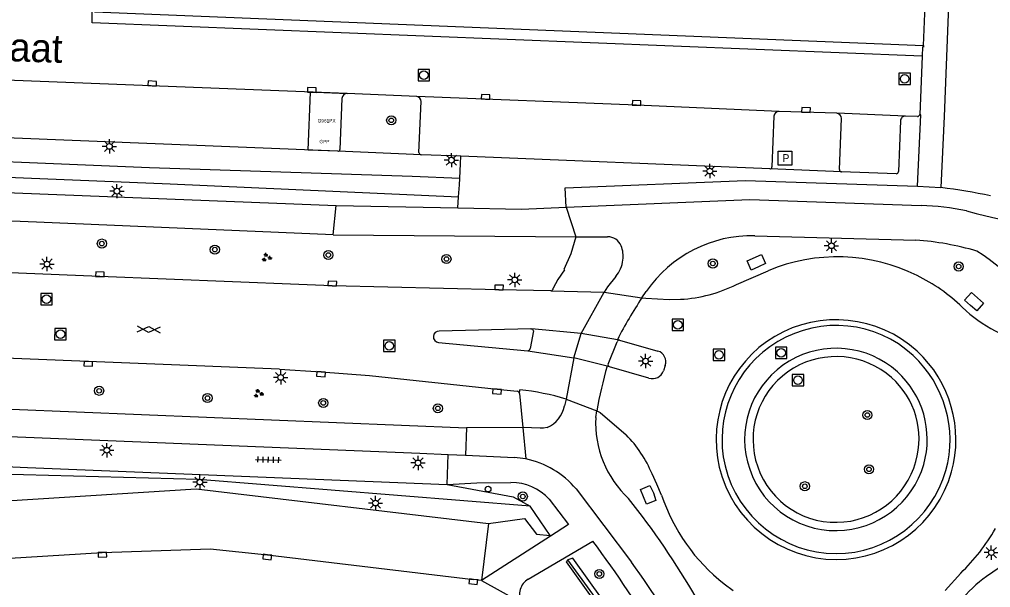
# Model space of a CAD drawing. Extents: x 132994 to 136000, y 393499 to 395512.
# Drawn here: x 133765.3 to 133850.3, y 394656.2 to 394705.8 of the extents above; entities that cross this region are included whole.
import ezdxf

# ---------------------------------------------------------------- set-up
doc = ezdxf.new("R2010")
doc.units = 0
for name, color, linetype in [('bp-anno-kenteken', 7, 'Continuous'), ('bp-grn-parkeervak', 7, 'Continuous'), ('gg-afsc-hekwerk', 7, 'Continuous'), ('gg-anno-openbare ruimte label', 7, 'Continuous'), ('gg-knt-verharding', 7, 'Continuous'), ('gg-knt-verharding nz', 7, 'Continuous'), ('gt-grn-groengrens', 7, 'Continuous'), ('gt-grn-weggrens', 7, 'Continuous'), ('gt-symb-boom', 7, 'Continuous'), ('gt-symb-brandput', 7, 'Continuous'), ('gt-symb-gesloten verharding', 7, 'Continuous'), ('gt-symb-groenvak', 7, 'Continuous'), ('gt-symb-kolk', 7, 'Continuous'), ('gt-symb-lichtmast', 7, 'Continuous'), ('gt-symb-rioolschacht', 7, 'Continuous'), ('gt-symb-tegel verharding', 7, 'Continuous'), ('gt-symb-verkeersbordpaal', 7, 'Continuous'), ('kenmerkpunt gehandicapten parkeerplaats', 7, 'Continuous')]:
    doc.layers.add(name, color=color, linetype=linetype)

# ---------------------------------------------------------------- blocks, each defined once
blk = doc.blocks.new('gt0-KOLK')
at = {"layer": 'gt-symb-kolk'}
blk.add_lwpolyline([(0, 0), (0.375, 0), (0.375, 0.4), (-0.375, 0.4), (-0.375, 0), (0, 0)], dxfattribs=at)
blk = doc.blocks.new('gt0-RS')
at = {"layer": 'gt-symb-rioolschacht'}
blk.add_lwpolyline([(-0.5, -0.5), (0.5, -0.5), (0.5, 0.5), (-0.5, 0.5)], close=True, dxfattribs=at)
blk.add_circle((0, 0), 0.375, dxfattribs=at)
blk = doc.blocks.new('gt0-BOOM')
at = {"layer": 'gt-symb-boom'}
for radius in [0.4, 0.2]:
    blk.add_circle((0, 0), radius, dxfattribs=at)
blk = doc.blocks.new('gt0-LMAST')
at = {"layer": 'gt-symb-lichtmast'}
for p, q in [((-0.182, 0.173), (-0.447, 0.438)), ((-0.005, 0.246), (-0.005, 0.621)), ((0.172, 0.173), (0.437, 0.438)), ((-0.255, -0.004), (-0.63, -0.004)), ((-0.182, -0.181), (-0.447, -0.446)), ((-0.005, -0.254), (-0.005, -0.629)), ((0.437, -0.446), (0.172, -0.181)), ((0.245, -0.004), (0.62, -0.004))]:
    blk.add_line(p, q, dxfattribs=at)
blk.add_circle((-0.005, -0.004), 0.25, dxfattribs=at)
blk = doc.blocks.new('gt0-BPUT')
at = {"layer": 'gt-symb-brandput'}
blk.add_lwpolyline([(-0.599, -0.599), (-0.599, 0.601), (0.601, 0.601), (0.601, -0.599)], close=True, dxfattribs=at)
blk.add_text('P', height=0.7, dxfattribs=at).set_placement((-0.233, -0.35))
blk = doc.blocks.new('gt0-VPAAL')
at = {"layer": 'gt-symb-verkeersbordpaal'}
blk.add_circle((0, 0), 0.25, dxfattribs=at)
blk = doc.blocks.new('gt0-GRVAK')
at = {"layer": 'gt-symb-groenvak'}
for p, q in [((-0.11, 0.189), (-0.228, 0.24)), ((-0.182, 0.153), (0.088, 0.153)), ((-0.091, 0.211), (-0.156, 0.322)), ((-0.047, 0.214), (-0.047, 0.393)), ((-0.004, 0.211), (0.061, 0.322)), ((0.015, 0.189), (0.133, 0.24)), ((0.262, -0.052), (0.197, 0.059)), ((0.305, -0.049), (0.305, 0.13)), ((0.349, -0.052), (0.414, 0.059)), ((-0.245, -0.228), (-0.363, -0.177)), ((-0.318, -0.264), (-0.047, -0.264)), ((-0.226, -0.206), (-0.291, -0.095)), ((-0.183, -0.203), (-0.183, -0.024)), ((-0.139, -0.206), (-0.074, -0.095)), ((-0.12, -0.228), (-0.002, -0.177)), ((0.243, -0.074), (0.125, -0.023)), ((0.17, -0.11), (0.441, -0.11)), ((0.368, -0.074), (0.486, -0.023))]:
    blk.add_line(p, q, dxfattribs=at)
blk = doc.blocks.new('gt0-GESVH1')
at = {"layer": 'gt-symb-gesloten verharding'}
for p, q in [((-0.992, -0.261), (0.008, 0.239)), ((0.008, -0.261), (-0.992, 0.239)), ((0.008, 0.239), (1.008, -0.261)), ((1.008, 0.239), (0.008, -0.261))]:
    blk.add_line(p, q, dxfattribs=at)
blk = doc.blocks.new('gt0-TEG1')
at = {"layer": 'gt-symb-tegel verharding'}
for p, q in [((-1.125, 0), (1.125, 0)), ((-0.9, -0.25), (-0.9, 0.25)), ((-0.45, -0.25), (-0.45, 0.25)), ((0, -0.25), (0, 0.25)), ((0.45, -0.25), (0.45, 0.25)), ((0.9, -0.25), (0.9, 0.25))]:
    blk.add_line(p, q, dxfattribs=at)

msp = doc.modelspace()

# ---------------------------------------------------------------- linework, layer by layer
at = {"layer": 'bp-grn-parkeervak'}
msp.add_line((133793.533, 394698.926), (133793.351, 394694.482), dxfattribs=at)
msp.add_lwpolyline([(133793.162, 394694.32), (133790.567, 394694.425), (133790.771, 394699.48), (133791.262, 394699.462), (133791.262, 394699.471), (133793.982, 394699.363)], dxfattribs=at)
for centre, radius, start, end in [((133793.991, 394698.905), 0.458, 91.12258, 177.32548), ((133793.169, 394694.503), 0.183, 267.75596, 353.44663)]:
    msp.add_arc(centre, radius, start, end, dxfattribs=at)
at = {"layer": 'gg-afsc-hekwerk'}
for p, q in [((133811.73, 394660.735), (133809.991, 394663.299)), ((133811.775, 394660.669), (133811.73, 394660.735))]:
    msp.add_line(p, q, dxfattribs=at)
for points in [[(133809.991, 394663.299), (133780.983, 394665.622), (133728.496, 394667.016)], [(133823.262, 394642.826), (133822.714, 394645.643), (133813.273, 394658.598)]]:
    msp.add_lwpolyline(points, dxfattribs=at)
at = {"layer": 'gg-knt-verharding'}
for p, q in [((133844.381, 394703.553), (133844.562, 394708.084)), ((133771.889, 394706.495), (133844.381, 394703.553)), ((133844.259, 394702.617), (133844.053, 394697.536)), ((133800.072, 394699.109), (133793.982, 394699.363)), ((133793.533, 394698.926), (133793.351, 394694.482)), ((133800.258, 394694.222), (133800.444, 394698.656)), ((133836.796, 394697.632), (133831.762, 394697.804)), ((133831.31, 394697.39), (133831.132, 394692.949)), ((133837.041, 394692.717), (133837.217, 394697.174)), ((133842.369, 394696.964), (133842.199, 394692.539)), ((133843.847, 394697.345), (133842.817, 394697.386)), ((133846.186, 394697.343), (133845.913, 394691.136)), ((133793.162, 394694.32), (133752.945, 394695.94)), ((133803.934, 394693.873), (133800.45, 394694.016)), ((133830.935, 394692.767), (133803.934, 394693.873)), ((133841.996, 394692.337), (133837.228, 394692.511)), ((133752.764, 394691.164), (133793.012, 394689.56)), ((133793.012, 394689.56), (133803.652, 394689.368)), ((133792.754, 394687.001), (133813.989, 394686.847)), ((133813.989, 394686.847), (133816.764, 394686.842)), ((133829.641, 394686.934), (133843.724, 394686.546)), ((133828.033, 394682.67), (133830.788, 394683.874)), ((133792.684, 394682.559), (133789.767, 394682.674)), ((133811.793, 394682.126), (133816.454, 394681.988)), ((133819.766, 394681.514), (133820.147, 394682.068)), ((133810.037, 394678.803), (133802.038, 394678.601)), ((133810.266, 394678.609), (133809.98, 394677.059)), ((133810.037, 394678.803), (133810.107, 394678.796)), ((133814.461, 394678.381), (133810.107, 394678.796)), ((133813.812, 394676.266), (133814.461, 394678.381)), ((133801.984, 394677.601), (133809.778, 394676.874)), ((133816.799, 394675.718), (133817.585, 394677.647)), ((133817.802, 394677.799), (133821.167, 394676.854)), ((133809.778, 394676.874), (133813.812, 394676.266)), ((133821.799, 394675.594), (133821.645, 394675.124)), ((133820.373, 394674.487), (133816.929, 394675.479)), ((133809.05, 394673.14), (133809.095, 394673.47)), ((133809.05, 394673.14), (133809.339, 394670.155)), ((133813.134, 394672.644), (133813.003, 394672.058)), ((133815.726, 394671.046), (133815.82, 394671.63)), ((133816.096, 394671.473), (133818.382, 394669.519)), ((133809.339, 394670.155), (133804.433, 394670.144)), ((133800.346, 394667.913), (133802.831, 394667.804)), ((133802.831, 394667.804), (133804.328, 394667.739)), ((133804.328, 394667.739), (133808.612, 394667.551)), ((133814.006, 394664.802), (133818.837, 394658.407)), ((133806.35, 394661.786), (133805.745, 394656.782)), ((133811.775, 394660.669), (133805.745, 394656.782)), ((133809.826, 394656.9), (133815.474, 394660.234)), ((133853.547, 394659.669), (133849.907, 394657.147)), ((133846.289, 394655.931), (133847.645, 394657.446)), ((133826.957, 394656.496), (133827.744, 394655.93))]:
    msp.add_line(p, q, dxfattribs=at)
for points in [[(133849.337, 394727.82), (133846.684, 394707.826), (133846.606, 394707.833), (133846.186, 394697.343)], [(133844.381, 394703.553), (133844.391, 394703.429), (133844.304, 394703.434), (133844.259, 394702.617)], [(133843.871, 394691.264), (133844.152, 394697.504), (133844.053, 394697.536)], [(133813.135, 394689.426), (133813.059, 394691.11), (133828.831, 394691.768), (133843.871, 394691.264)], [(133813.135, 394689.426), (133829.202, 394690.095), (133844.185, 394689.571)], [(133792.754, 394687.001), (133766.808, 394688.109), (133731.72, 394689.534)], [(133803.652, 394689.368), (133809.223, 394689.268), (133813.135, 394689.426)], [(133813.989, 394686.847), (133813.555, 394685.36), (133812.938, 394683.981), (133812.98, 394683.953), (133812.422, 394683.114), (133812.008, 394682.334)], [(133830.576, 394684.493), (133829.955, 394684.2), (133829.321, 394683.917), (133828.957, 394684.731), (133830.212, 394685.282), (133830.576, 394684.493)], [(133789.767, 394682.674), (133772.353, 394683.357), (133738.902, 394684.743)], [(133817.477, 394683.378), (133816.763, 394682.456), (133816.454, 394681.988)], [(133811.793, 394682.126), (133807.265, 394682.212), (133792.684, 394682.559)], [(133820.108, 394681.478), (133822.139, 394681.369), (133823.148, 394681.376)], [(133849.063, 394680.364), (133848.485, 394680.843), (133847.979, 394681.304), (133848.584, 394681.956), (133849.626, 394681.036), (133849.063, 394680.364)], [(133788.073, 394675.271), (133762.589, 394676.287), (133738.597, 394677.272)], [(133788.073, 394675.271), (133791.712, 394675.033), (133795.929, 394674.716), (133807.106, 394673.514), (133808.858, 394673.338)], [(133728.982, 394673.24), (133736.189, 394672.925), (133804.433, 394670.144)], [(133728.768, 394670.857), (133763.723, 394669.408), (133800.346, 394667.913)], [(133811.483, 394670.16), (133811.163, 394670.095), (133810.851, 394670.094), (133809.339, 394670.155)], [(133728.533, 394668.252), (133762.121, 394666.858), (133766.041, 394666.677), (133802.717, 394665.195)], [(133802.717, 394665.195), (133805.335, 394665.337), (133808.311, 394665.348)], [(133821.483, 394664.264), (133821.078, 394665.212), (133820.648, 394666.123)], [(133752.658, 394663.035), (133780.79, 394664.799), (133806.35, 394661.786)], [(133820.444, 394665.089), (133820.763, 394664.45), (133820.984, 394663.795), (133820.162, 394663.477), (133819.628, 394664.755), (133820.444, 394665.089)], [(133811.658, 394663.905), (133813.343, 394661.68), (133811.775, 394660.669)]]:
    msp.add_lwpolyline(points, dxfattribs=at)
for centre, radius, start, end in [((133793.991, 394698.905), 0.458, 91.12258, 177.32548), ((133800.025, 394698.691), 0.42, 355.19104, 83.5941), ((133831.752, 394697.361), 0.443, 88.67765, 176.29731), ((133836.758, 394697.174), 0.459, 359.97242, 85.20689), ((133842.802, 394696.953), 0.434, 88.07819, 178.49826), ((133843.839, 394697.56), 0.215, 272.09034, 353.58207), ((133793.169, 394694.503), 0.183, 267.75596, 353.44663), ((133800.467, 394694.224), 0.209, 180.67384, 265.29697), ((133830.938, 394692.961), 0.194, 269.14484, 356.32224), ((133837.239, 394692.709), 0.198, 177.66235, 266.80191), ((133841.97, 394692.566), 0.231, 276.46808, 353.24898), ((133841.985, 394654.441), 36.904, 77.05685, 83.89002), ((133843.424, 394665.722), 23.861, 78.59515, 88.17171), ((133857.418, 394720.691), 32.913, 253.62995, 278.07403), ((133816.771, 394685.57), 1.272, 22.22596, 90.32699), ((133829.404, 394675.702), 11.235, 88.79047, 145.48291), ((133815.587, 394685.136), 2.533, 352.45941, 21.16816), ((133841.952, 394661.396), 25.212, 73.68435, 85.96999), ((133836.841, 394669.313), 15.769, 63.73432, 112.57386), ((133839.262, 394669.996), 18.406, 25.13507, 57.92871), ((133815.38, 394685.139), 2.739, 319.96991, 352.9654), ((133836.854, 394669.292), 15.783, 46.19412, 63.80824), ((133811.789, 394682.345), 0.219, 270.97988, 357.12398), ((133822.437, 394693.929), 12.573, 273.24334, 296.4296), ((133856.165, 394689.36), 12.067, 225.9806, 259.74876), ((133836.721, 394669.033), 10.557, 47.69366, 120.45357), ((133836.749, 394669.171), 9.918, 47.35731, 120.99705), ((133802.022, 394678.1), 0.501, 88.19801, 265.62005), ((133810.051, 394678.588), 0.216, 5.67214, 75.07472), ((133836.776, 394669.101), 10.526, 120.89737, 193.24071), ((133817.801, 394677.57), 0.229, 89.7085, 160.31097), ((133836.714, 394669.114), 9.949, 120.65698, 193.40108), ((133809.769, 394677.086), 0.213, 272.3592, 352.61029), ((133820.848, 394675.905), 1.001, 341.87395, 71.40158), ((133836.747, 394669.065), 8.027, 48.1636, 120.73446), ((133836.738, 394669.047), 7.322, 48.58188, 120.51662), ((133836.673, 394669.087), 10.03, 344.51827, 47.36049), ((133836.695, 394669.098), 10.526, 344.45302, 47.34749), ((133816.994, 394675.669), 0.201, 165.97333, 251.11313), ((133836.683, 394669.13), 7.938, 120.58044, 194.28352), ((133820.684, 394675.455), 1.017, 252.20533, 340.99682), ((133836.725, 394669.126), 7.248, 120.74035, 194.47501), ((133836.677, 394669.121), 8.032, 344.28468, 47.52388), ((133836.836, 394669.175), 7.162, 343.96174, 48.49513), ((133808.819, 394673.108), 0.233, 7.79557, 80.44162), ((133806.635, 394651.153), 22.453, 73.17447, 83.7096), ((133810.287, 394672.675), 2.785, 295.42677, 347.19474), ((133824.75, 394670.573), 9.037, 177.00004, 227.08398), ((133810.821, 394662.02), 10.649, 22.66231, 44.76453), ((133808.06, 394659.894), 7.677, 78.39749, 85.87633), ((133808.047, 394659.774), 7.797, 40.15349, 78.47955), ((133836.712, 394669.11), 7.96, 194.0873, 270.8349), ((133836.706, 394669.1), 7.223, 194.31518, 271.01688), ((133836.728, 394669.131), 7.254, 270.83847, 344.5268), ((133836.772, 394669.161), 10.536, 193.56236, 269.85367), ((133836.783, 394669.168), 10.029, 193.60928, 269.74111), ((133836.708, 394669.153), 10.014, 270.17363, 344.1009), ((133836.734, 394669.12), 10.495, 270.06189, 344.28416), ((133836.716, 394669.153), 8.004, 270.8021, 343.98729), ((133808.372, 394660.887), 4.461, 42.56788, 90.78725), ((133764.488, 394620.756), 69.238, 29.86457, 38.60312), ((133837.079, 394669.442), 16.433, 198.36517, 231.97846), ((133836.038, 394669.632), 16.829, 313.60544, 330.41373), ((133715.1, 394586.114), 124.774, 26.68684, 36.44362), ((133747.421, 394606.62), 88.216, 22.94305, 35.94773), ((133810.55, 394655.593), 1.494, 118.96876, 209.86491), ((133855.972, 394648.509), 10.555, 125.0752, 159.66962)]:
    msp.add_arc(centre, radius, start, end, dxfattribs=at)
at = {"layer": 'gg-knt-verharding nz'}
for p, q in [((133793.982, 394699.363), (133753.136, 394700.981)), ((133842.817, 394697.386), (133836.796, 394697.632)), ((133814.461, 394678.381), (133816.454, 394681.988)), ((133816.454, 394681.988), (133819.766, 394681.514)), ((133819.766, 394681.514), (133820.108, 394681.478)), ((133817.618, 394677.842), (133814.461, 394678.381)), ((133817.802, 394677.799), (133817.618, 394677.842)), ((133813.812, 394676.266), (133813.134, 394672.644)), ((133816.729, 394675.531), (133813.812, 394676.266)), ((133816.929, 394675.479), (133816.729, 394675.531)), ((133813.134, 394672.644), (133815.82, 394671.63)), ((133815.82, 394671.63), (133816.096, 394671.473)), ((133787.019, 394659.047), (133805.044, 394656.882)), ((133805.745, 394656.782), (133805.044, 394656.882)), ((133805.745, 394656.782), (133809.254, 394654.849))]:
    msp.add_line(p, q, dxfattribs=at)
for points in [[(133844.259, 394702.617), (133771.681, 394705.557), (133771.697, 394706.519)], [(133831.762, 394697.804), (133819.286, 394698.333), (133800.072, 394699.109)], [(133752.967, 394658.057), (133757.801, 394658.323), (133772.574, 394659.249), (133782.016, 394659.569), (133787.019, 394659.047)]]:
    msp.add_lwpolyline(points, dxfattribs=at)
for centre, radius, start, end in [((133851.869, 394660.271), 38.495, 146.50623, 152.84129), ((133846.794, 394666.469), 31.401, 163.22634, 170.53997)]:
    msp.add_arc(centre, radius, start, end, dxfattribs=at)
at = {"layer": 'gt-grn-groengrens'}
for p, q in [((133800.45, 394694.016), (133793.162, 394694.32)), ((133803.909, 394693.255), (133803.934, 394693.873)), ((133803.831, 394691.932), (133803.909, 394693.255)), ((133837.228, 394692.511), (133830.935, 394692.767)), ((133803.808, 394691.387), (133803.831, 394691.932)), ((133803.726, 394690.326), (133803.808, 394691.387)), ((133803.652, 394689.368), (133803.726, 394690.326))]:
    msp.add_line(p, q, dxfattribs=at)
for points in [[(133803.831, 394691.932), (133799.665, 394692.108), (133776.708, 394692.873), (133752.866, 394693.858)], [(133752.815, 394692.517), (133778.51, 394691.466), (133803.726, 394690.326)], [(133802.717, 394665.195), (133808.49, 394664.116), (133809.991, 394663.299)], [(133806.35, 394661.786), (133809.494, 394662.199), (133810.556, 394660.853), (133811.73, 394660.735)], [(133813.273, 394658.598), (133813.135, 394658.413), (133822.392, 394645.454), (133822.891, 394643.115), (133822.848, 394642.917)], [(133824.473, 394641.192), (133823.677, 394642.927), (133823.087, 394645.679), (133813.706, 394658.758), (133813.273, 394658.598)]]:
    msp.add_lwpolyline(points, dxfattribs=at)
at = {"layer": 'gt-grn-weggrens'}
for p, q in [((133843.871, 394691.264), (133845.913, 394691.136)), ((133792.754, 394687.001), (133793.012, 394689.56)), ((133813.135, 394689.426), (133813.989, 394686.847)), ((133804.433, 394670.144), (133804.328, 394667.739)), ((133809.339, 394670.155), (133809.604, 394667.414)), ((133802.717, 394665.195), (133802.831, 394667.804))]:
    msp.add_line(p, q, dxfattribs=at)

# ---------------------------------------------------------------- block references
at = {"layer": 'gt-symb-boom'}
for p in [(133797.839, 394697.023), (133772.536, 394686.247), (133782.413, 394685.72), (133792.34, 394685.243), (133802.668, 394684.896), (133825.961, 394684.507), (133847.46, 394684.246), (133772.294, 394673.377), (133781.771, 394672.738), (133791.893, 394672.316), (133801.919, 394671.839), (133839.471, 394671.258), (133839.617, 394666.512), (133834.006, 394665.032), (133809.343, 394664.138), (133816.037, 394657.364)]:
    msp.add_blockref('gt0-BOOM', p, dxfattribs=at)
at = {"layer": 'gt-symb-brandput'}
msp.add_blockref('gt0-BPUT', (133832.27, 394693.714), dxfattribs=at)
at = {"layer": 'gt-symb-gesloten verharding', "rotation": -2.292900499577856}
msp.add_blockref('gt0-GESVH1', (133776.629, 394678.746), dxfattribs=at)
at = {"layer": 'gt-symb-groenvak'}
for p in [(133786.927, 394685.035), (133786.217, 394673.131)]:
    msp.add_blockref('gt0-GRVAK', p, dxfattribs=at)
at = {"layer": 'gt-symb-kolk'}
for p, rotation in [((133776.929, 394700.044), -2.3328628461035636), ((133790.887, 394699.476), -2.0906300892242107), ((133806.079, 394698.872), -2.340926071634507), ((133819.286, 394698.333), -2.4215531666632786), ((133834.101, 394697.73), -2.0825652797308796), ((133772.353, 394683.357), -2.35015952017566), ((133792.684, 394682.559), -2.235636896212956), ((133807.263, 394682.212), -1.0894489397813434), ((133771.353, 394675.934), 177.70709950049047), ((133791.71, 394675.033), 176.26107557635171), ((133807.11, 394673.514), 174.36648958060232), ((133772.574, 394659.249), -176.41460461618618), ((133787.019, 394659.047), 174.04210119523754), ((133805.044, 394656.882), 173.14825238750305)]:
    msp.add_blockref('gt0-KOLK', p, dxfattribs=dict(at, rotation=rotation))
at = {"layer": 'gt-symb-lichtmast'}
for p in [(133773.2, 394694.748), (133803.103, 394693.541), (133825.707, 394692.587), (133773.86, 394690.833), (133836.341, 394686.059), (133767.74, 394684.46), (133808.642, 394683.077), (133820.09, 394675.974), (133788.176, 394674.549), (133772.973, 394668.178), (133800.186, 394667.071), (133781.109, 394665.394), (133796.469, 394663.561), (133850.32, 394659.231)]:
    msp.add_blockref('gt0-LMAST', p, dxfattribs=at)
at = {"layer": 'gt-symb-rioolschacht'}
for p in [(133800.699, 394700.976), (133842.737, 394700.641), (133822.909, 394679.138), (133797.67, 394677.316), (133826.5, 394676.526), (133831.937, 394676.704), (133833.409, 394674.304)]:
    msp.add_blockref('gt0-RS', p, dxfattribs=at)
for p, rotation in [((133767.689, 394681.387), -0.11459140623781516), ((133768.909, 394678.329), 179.36977184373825)]:
    msp.add_blockref('gt0-RS', p, dxfattribs=dict(at, rotation=rotation))
at = {"layer": 'gt-symb-tegel verharding', "rotation": -1.4320961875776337}
msp.add_blockref('gt0-TEG1', (133787.094, 394667.35), dxfattribs=at)
at = {"layer": 'gt-symb-verkeersbordpaal'}
msp.add_blockref('gt0-VPAAL', (133806.311, 394664.779), dxfattribs=at)

# ---------------------------------------------------------------- texts
at = {"layer": 'bp-anno-kenteken'}
msp.add_text('G961PX', height=0.3, dxfattribs=at).set_placement((133791.405, 394696.83))
at = {"layer": 'gg-anno-openbare ruimte label'}
msp.add_text('Karawankenstraat', height=2.5, rotation=358.1, dxfattribs=at).set_placement((133742.125, 394702.932))
at = {"layer": 'kenmerkpunt gehandicapten parkeerplaats'}
msp.add_text('GPP', height=0.3, dxfattribs=at).set_placement((133791.561, 394695.015))

doc.saveas('drawing.dxf')
